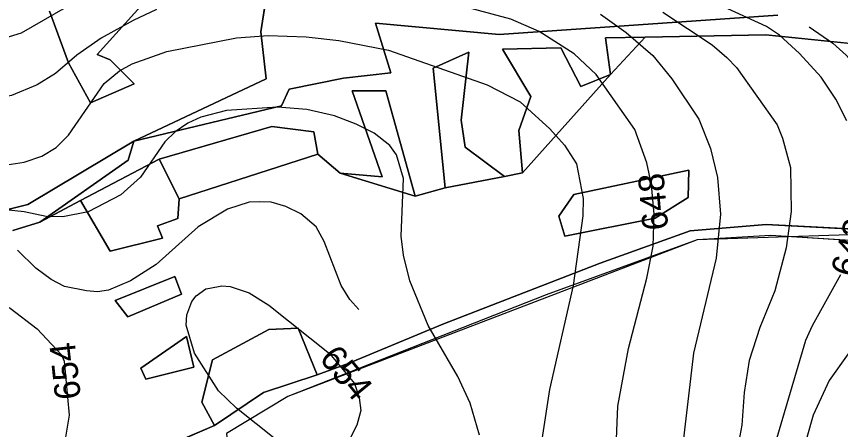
# Model space of a CAD drawing. Extents: x -709418 to -703832, y -1161719 to -1157826.
# Drawn here: x -705972.5 to -705715.8, y -1160342.6 to -1160213.8 of the extents above; entities that cross this region are included whole.
import ezdxf

# ---------------------------------------------------------------- set-up
doc = ezdxf.new("R2010")
doc.units = 0
for name, color, linetype in [('102_obvod PÚ', 7, 'Continuous'), ('120_vrstevnice hlavní', 7, 'Continuous'), ('121_vrstevnice hlavní_popis', 7, 'Continuous'), ('122_vrstevnice základní', 7, 'Continuous'), ('124_vrstevnice doplňková', 7, 'Continuous'), ('206_TTP_KN', 7, 'Continuous'), ('207_lesní pozemek_KN', 7, 'Continuous'), ('210_ostatní plocha_KN', 7, 'Continuous'), ('609_LBC_stav', 7, 'Continuous')]:
    doc.layers.add(name, color=color, linetype=linetype)

msp = doc.modelspace()

# ---------------------------------------------------------------- linework, layer by layer
at = {"layer": '102_obvod PÚ'}
for points in [[(-705735.28, -1160213.34), (-705822.05, -1160219.43), (-705860.61, -1160215.91), (-705855.83, -1160231.34), (-705870.62, -1160233.07), (-705887.55, -1160236.42), (-705889.92, -1160241.63), (-705935.88, -1160252.66), (-705894.69, -1160233.2), (-705896.39, -1160218.62), (-705894.1, -1160203.86)], [(-705894.1, -1160203.86), (-705896.39, -1160218.62), (-705894.69, -1160233.2), (-705935.88, -1160252.66), (-705889.92, -1160241.63), (-705887.55, -1160236.42), (-705870.62, -1160233.07), (-705855.83, -1160231.34), (-705860.61, -1160215.91), (-705822.05, -1160219.43), (-705735.28, -1160213.34)], [(-705690.92, -1160285.05), (-705737.52, -1160282.05), (-705760.43, -1160283.48), (-705807.45, -1160300.6), (-705887.96, -1160332.34), (-705907.02, -1160343.87), (-705903.72, -1160383.44), (-705891.24, -1160380.51), (-705892.88, -1160372.23), (-705870.76, -1160364.88), (-705872.61, -1160374.66), (-705865.48, -1160396.64), (-705851.7, -1160404.74), (-705842.93, -1160422.79), (-705826.94, -1160427.36), (-705803.04, -1160451.48), (-705774.99, -1160452.69), (-705772.92, -1160476.52), (-705777.28, -1160481.34), (-705775.29, -1160489.21), (-705766.13, -1160501.98), (-705760.34, -1160538.38)]]:
    msp.add_lwpolyline(points, dxfattribs=at)
at = {"layer": '120_vrstevnice hlavní'}
for points in [[(-705975.46, -1160260.05), (-705970.05, -1160259.2), (-705964.63, -1160257.34), (-705960.07, -1160254.64), (-705956.22, -1160250.79), (-705945.11, -1160234.69), (-705940.41, -1160230.7), (-705936.42, -1160228.56), (-705925.59, -1160224.71), (-705903.93, -1160220.44), (-705894.05, -1160219.72), (-705882.27, -1160220.15), (-705872.01, -1160221.29), (-705856.62, -1160224.29), (-705825.84, -1160235.12), (-705815.58, -1160240.39), (-705806.32, -1160248.8), (-705801.76, -1160253.93), (-705798.06, -1160259.77), (-705795.92, -1160270.6), (-705796.06, -1160276.01), (-705799.05, -1160297.67), (-705806.46, -1160330.16), (-705810.6, -1160357.23)], [(-705713.42, -1160319.05), (-705719.26, -1160327.31), (-705724.24, -1160338.14), (-705730.37, -1160359.8), (-705743.34, -1160386.87), (-705746.33, -1160397.7), (-705747.68, -1160404.55), (-705748.18, -1160413.95), (-705748.04, -1160419.36), (-705745.48, -1160430.19), (-705743.2, -1160435.61), (-705740.06, -1160441.02), (-705730.23, -1160453.42), (-705717.97, -1160466.81), (-705712.7, -1160474.08)]]:
    msp.add_lwpolyline(points, dxfattribs=at)
at = {"layer": '122_vrstevnice základní'}
for points in [[(-706139.33, -1160207.47), (-706125.22, -1160217.59), (-706114.25, -1160227.28), (-706091.31, -1160251.07), (-706082.33, -1160258.06), (-706072.36, -1160264.33), (-706060.53, -1160270.31), (-706052.12, -1160273.87), (-706033.99, -1160279.91), (-705988.29, -1160297.96), (-705974.46, -1160304.8), (-705966.06, -1160311.21), (-705960.04, -1160317.65), (-705958.49, -1160319.28), (-705957.65, -1160321.32), (-705956.08, -1160338.14), (-705957.22, -1160344.98), (-705958.93, -1160349.54), (-705966.91, -1160361.22), (-705989.85, -1160389.44), (-706003.82, -1160411.67), (-706011.94, -1160427.48), (-706030.47, -1160456.55)], [(-705928.82, -1160211.57), (-705936.13, -1160215.02), (-705946.11, -1160220.58), (-705953.66, -1160225.85), (-705960.36, -1160231.55), (-705966.06, -1160235.12), (-705974.04, -1160238.39), (-705980.02, -1160239.68), (-705984.01, -1160239.82), (-706001.97, -1160238.25), (-706021.92, -1160234.4), (-706054.12, -1160225.43), (-706068.94, -1160219.87), (-706079.48, -1160214.45), (-706090.6, -1160206.9)], [(-706008.52, -1160223.43), (-705998.55, -1160224.43), (-705988.86, -1160223.72), (-705981.16, -1160222.01), (-705970.9, -1160218.87), (-705953.8, -1160209.04)], [(-705818.43, -1160214.6), (-705834.39, -1160210.32)], [(-705713.84, -1160246.37), (-705717.26, -1160239.53), (-705721.82, -1160232.69), (-705728.52, -1160225.28), (-705734.79, -1160219.58), (-705738.78, -1160216.88), (-705752.17, -1160210.75)], [(-705790.51, -1160213.03), (-705782.53, -1160218.73), (-705774.26, -1160226), (-705768.28, -1160233.26), (-705759.87, -1160245.8), (-705756.31, -1160254.92), (-705754.03, -1160264.04), (-705753.17, -1160275.44), (-705754.45, -1160289.12), (-705761.58, -1160318.76), (-705765.28, -1160350.68)], [(-705771.12, -1160212.46), (-705755.74, -1160222.58), (-705751.2, -1160226.61), (-705748.14, -1160229.72), (-705735.45, -1160247.53), (-705733.79, -1160251.79), (-705731.37, -1160260.91), (-705731.08, -1160274.59), (-705732.65, -1160285.99), (-705736.21, -1160299.38), (-705740.92, -1160310.78), (-705744.19, -1160321.04), (-705745.76, -1160331.02), (-705746.47, -1160341.27), (-705748.33, -1160351.25)], [(-705785.66, -1160348.11), (-705785.09, -1160335.29), (-705781.81, -1160317.33), (-705776.11, -1160295.39), (-705774.12, -1160285.42), (-705773.83, -1160275.44), (-705774.69, -1160266.32), (-705776.11, -1160259.48), (-705779.82, -1160249.08), (-705791.93, -1160231.84), (-705798.77, -1160225.43), (-705809.6, -1160218.44), (-705818.43, -1160214.6)], [(-705828.27, -1160344.41), (-705831.11, -1160334.44), (-705834.96, -1160326.03), (-705844.22, -1160310.21), (-705849.92, -1160296.25), (-705851.92, -1160288.27), (-705852.63, -1160282.28), (-705851.92, -1160264.33), (-705854.06, -1160256.92), (-705856.19, -1160254.07), (-705861.04, -1160250.22), (-705866.6, -1160247.37), (-705873.44, -1160244.81), (-705881.99, -1160242.81), (-705891.11, -1160242.1), (-705907.07, -1160243.09), (-705915.05, -1160245.23), (-705919.12, -1160247.05), (-705923.02, -1160249.79), (-705926.3, -1160252.93), (-705933.85, -1160263.9), (-705939.98, -1160269.46), (-705950.1, -1160274.73), (-705958.08, -1160276.3), (-705963.21, -1160276.15), (-705970.05, -1160274.73), (-705994.5, -1160272.13)], [(-705715.41, -1160484.05), (-705720.25, -1160476.36), (-705726.81, -1160468.81), (-705737.5, -1160458.98), (-705744.76, -1160451), (-705752.25, -1160438.07), (-705754.15, -1160433.64), (-705756.73, -1160424.21), (-705757.64, -1160418.97), (-705757.59, -1160415.09), (-705757.45, -1160408.25), (-705754.88, -1160394.57), (-705751.18, -1160383.17), (-705740.06, -1160358.09), (-705736.64, -1160348.97), (-705726.52, -1160314.77), (-705724.53, -1160310.21), (-705715.7, -1160294.25)], [(-705909.49, -1160330.59), (-705917.04, -1160318.76), (-705919.6, -1160310.04), (-705919.44, -1160306.86), (-705917.89, -1160302.73), (-705916.48, -1160300.97), (-705913.45, -1160298.77), (-705912.2, -1160298.53), (-705908.49, -1160297.81), (-705905.93, -1160297.96), (-705899.94, -1160299.95), (-705893.81, -1160303.8), (-705875, -1160318.9), (-705867.17, -1160328.31), (-705865.74, -1160332.73), (-705865.17, -1160336.72), (-705866.45, -1160341.27), (-705868.82, -1160345.93)], [(-705891.68, -1160345.69), (-705903.93, -1160336), (-705909.49, -1160330.59)]]:
    msp.add_lwpolyline(points, dxfattribs=at)
at = {"layer": '124_vrstevnice doplňková'}
for points in [[(-705725.51, -1160216.98), (-705718.12, -1160222.15), (-705713.98, -1160225.85), (-705709.99, -1160230.41), (-705703.3, -1160239.82), (-705698.17, -1160252.64), (-705696.17, -1160262.62), (-705696.46, -1160274.02), (-705697.74, -1160280.86), (-705702.3, -1160290.4)], [(-705865.86, -1160305.15), (-705868.59, -1160302.09), (-705871.3, -1160297.67), (-705876.57, -1160283.99), (-705879.14, -1160279.43), (-705883.84, -1160275.3), (-705888.54, -1160273.02), (-705893.1, -1160271.74), (-705896.77, -1160271.62), (-705899.94, -1160271.74), (-705906.78, -1160273.87), (-705915.9, -1160279.43), (-705929.01, -1160291.12), (-705936.99, -1160296.25), (-705943.83, -1160299.1), (-705947.24, -1160299.72), (-705950.67, -1160299.38), (-705957.51, -1160297.96), (-705961.64, -1160295.82), (-705966.48, -1160292.26), (-705972.18, -1160286.7)]]:
    msp.add_lwpolyline(points, dxfattribs=at)
at = {"layer": '206_TTP_KN'}
for points in [[(-705894.1, -1160203.86), (-705896.39, -1160218.62), (-705894.69, -1160233.2), (-705935.88, -1160252.66), (-705968.89, -1160272.43), (-706006.54, -1160281.78), (-706042.5, -1160286.16), (-706098.09, -1160287.95), (-706104.62, -1160239.75), (-706122.98, -1160227.78), (-706120.14, -1160191.95)], [(-705962.19, -1160212.13), (-705956.28, -1160228.2), (-705949.41, -1160240.72), (-705935.86, -1160234.78), (-705943.25, -1160227.28), (-705947.39, -1160225.61), (-705932.85, -1160209.48)], [(-705973.63, -1160280.5), (-705965.16, -1160277.89), (-705952.5, -1160271.23), (-705943.28, -1160287), (-705926.96, -1160282.94), (-705928.59, -1160279.04), (-705922.18, -1160276.8), (-705921.76, -1160270.62), (-705878.58, -1160256.78), (-705871.67, -1160262.68), (-705848.28, -1160269.81), (-705838.93, -1160267.21), (-705820.39, -1160263.68), (-705814.83, -1160262.54), (-705787.37, -1160231.9), (-705776.61, -1160220.22), (-705739.07, -1160219.48), (-705709.54, -1160222.57)], [(-705803.55, -1160276.02), (-705801.64, -1160282.32), (-705773.54, -1160276.72), (-705763.21, -1160270.28), (-705763, -1160261.72), (-705798.81, -1160269.29), (-705803.55, -1160276.02)], [(-705690.96, -1160281.19), (-705738.93, -1160278.67), (-705762.57, -1160280.65), (-705790.67, -1160290.77), (-705839.64, -1160309.74), (-705869.16, -1160321.98), (-705878.78, -1160325.59), (-705884.75, -1160311.03), (-705893.91, -1160311.39), (-705911.39, -1160320.83), (-705914.75, -1160334.07), (-705910.77, -1160341.38), (-705941.4, -1160354.48), (-705982.09, -1160362.19), (-705988.37, -1160348.37), (-705988.94, -1160332.52), (-705995.59, -1160334.33), (-705996.39, -1160363.25), (-706013.23, -1160364.81), (-706055.06, -1160369.06), (-706082.24, -1160372.31), (-706147.28, -1160379.75), (-706201.14, -1160395.86)], [(-705941.7, -1160302.34), (-705937.81, -1160307.51), (-705921.11, -1160300.36), (-705923.16, -1160294.84), (-705941.7, -1160302.34)], [(-705933.7, -1160323.44), (-705932.22, -1160326.9), (-705917.21, -1160323.22), (-705919.48, -1160313.6), (-705933.7, -1160323.44)]]:
    msp.add_lwpolyline(points, dxfattribs=at)
at = {"layer": '207_lesní pozemek_KN'}
for p, q in [((-705896.39, -1160218.62), (-705894.1, -1160203.86)), ((-705735.28, -1160213.34), (-705822.05, -1160219.43)), ((-705822.05, -1160219.43), (-705860.61, -1160215.91)), ((-705860.61, -1160215.91), (-705855.83, -1160231.34)), ((-705894.69, -1160233.2), (-705896.39, -1160218.62)), ((-705789, -1160220.47), (-705776.61, -1160220.22)), ((-705787.37, -1160231.9), (-705789, -1160220.47)), ((-705776.61, -1160220.22), (-705787.37, -1160231.9)), ((-705821.09, -1160223.97), (-705802.94, -1160223.51)), ((-705812.28, -1160238.73), (-705821.09, -1160223.97)), ((-705802.94, -1160223.51), (-705796.61, -1160235.61)), ((-705842.71, -1160229.92), (-705831.57, -1160224.89)), ((-705831.57, -1160224.89), (-705833.94, -1160246.09)), ((-705855.83, -1160231.34), (-705870.62, -1160233.07)), ((-705838.93, -1160267.21), (-705842.71, -1160229.92)), ((-705787.37, -1160231.9), (-705814.83, -1160262.54)), ((-705796.61, -1160235.61), (-705787.37, -1160231.9)), ((-705935.88, -1160252.66), (-705894.69, -1160233.2)), ((-705870.62, -1160233.07), (-705887.55, -1160236.42)), ((-705887.55, -1160236.42), (-705889.92, -1160241.63)), ((-705858.51, -1160263.85), (-705867.86, -1160236.96)), ((-705867.86, -1160236.96), (-705857.46, -1160236.96)), ((-705857.46, -1160236.96), (-705848.28, -1160269.81)), ((-705816, -1160249.31), (-705812.28, -1160238.73)), ((-705889.92, -1160241.63), (-705935.88, -1160252.66)), ((-705833.94, -1160246.09), (-705832.74, -1160254.55)), ((-705927.98, -1160258.34), (-705892.92, -1160248.08)), ((-705892.92, -1160248.08), (-705879.89, -1160249.77)), ((-705879.89, -1160249.77), (-705878.58, -1160256.78)), ((-705814.83, -1160262.54), (-705816, -1160249.31)), ((-705832.74, -1160254.55), (-705820.39, -1160263.68)), ((-705878.58, -1160256.78), (-705921.76, -1160270.62)), ((-705952.5, -1160271.23), (-705927.98, -1160258.34)), ((-705927.98, -1160258.34), (-705921.76, -1160270.62)), ((-705921.76, -1160270.62), (-705927.98, -1160258.34)), ((-705871.67, -1160262.68), (-705858.51, -1160263.85)), ((-705848.28, -1160269.81), (-705871.67, -1160262.68)), ((-705820.39, -1160263.68), (-705838.93, -1160267.21)), ((-705921.76, -1160270.62), (-705922.18, -1160276.8)), ((-705943.28, -1160287), (-705952.5, -1160271.23)), ((-705922.18, -1160276.8), (-705928.59, -1160279.04)), ((-705928.59, -1160279.04), (-705926.96, -1160282.94)), ((-705926.96, -1160282.94), (-705943.28, -1160287)), ((-705911.39, -1160320.83), (-705893.91, -1160311.39)), ((-705893.91, -1160311.39), (-705884.75, -1160311.03)), ((-705884.75, -1160311.03), (-705878.78, -1160325.59)), ((-705914.75, -1160334.07), (-705911.39, -1160320.83)), ((-705878.78, -1160325.59), (-705895.56, -1160331.04)), ((-705895.56, -1160331.04), (-705910.77, -1160341.38)), ((-705910.77, -1160341.38), (-705914.75, -1160334.07))]:
    msp.add_line(p, q, dxfattribs=at)
at = {"layer": '210_ostatní plocha_KN'}
for p, q in [((-705932.85, -1160209.48), (-705947.39, -1160225.61)), ((-705956.28, -1160228.2), (-705962.19, -1160212.13)), ((-705822.05, -1160219.43), (-705735.28, -1160213.34)), ((-705855.83, -1160231.34), (-705860.61, -1160215.91)), ((-705860.61, -1160215.91), (-705822.05, -1160219.43)), ((-705776.61, -1160220.22), (-705789, -1160220.47)), ((-705789, -1160220.47), (-705787.37, -1160231.9)), ((-705739.07, -1160219.48), (-705776.61, -1160220.22)), ((-705709.54, -1160222.57), (-705739.07, -1160219.48)), ((-705802.94, -1160223.51), (-705821.09, -1160223.97)), ((-705821.09, -1160223.97), (-705812.28, -1160238.73)), ((-705796.61, -1160235.61), (-705802.94, -1160223.51)), ((-705947.39, -1160225.61), (-705943.25, -1160227.28)), ((-705831.57, -1160224.89), (-705842.71, -1160229.92)), ((-705833.94, -1160246.09), (-705831.57, -1160224.89)), ((-705949.41, -1160240.72), (-705956.28, -1160228.2)), ((-705943.25, -1160227.28), (-705935.86, -1160234.78)), ((-705870.62, -1160233.07), (-705855.83, -1160231.34)), ((-705842.71, -1160229.92), (-705838.93, -1160267.21)), ((-705787.37, -1160231.9), (-705796.61, -1160235.61)), ((-705887.55, -1160236.42), (-705870.62, -1160233.07)), ((-705935.86, -1160234.78), (-705949.41, -1160240.72)), ((-705889.92, -1160241.63), (-705887.55, -1160236.42)), ((-705857.46, -1160236.96), (-705867.86, -1160236.96)), ((-705867.86, -1160236.96), (-705858.51, -1160263.85)), ((-705848.28, -1160269.81), (-705857.46, -1160236.96)), ((-705812.28, -1160238.73), (-705816, -1160249.31)), ((-705935.88, -1160252.66), (-705889.92, -1160241.63)), ((-705832.74, -1160254.55), (-705833.94, -1160246.09)), ((-705892.92, -1160248.08), (-705927.98, -1160258.34)), ((-705879.89, -1160249.77), (-705892.92, -1160248.08)), ((-705878.58, -1160256.78), (-705879.89, -1160249.77)), ((-705816, -1160249.31), (-705814.83, -1160262.54)), ((-705968.89, -1160272.43), (-705935.88, -1160252.66)), ((-705935.88, -1160252.66), (-705937.64, -1160258.64)), ((-705937.64, -1160258.64), (-705935.88, -1160252.66)), ((-705820.39, -1160263.68), (-705832.74, -1160254.55)), ((-705871.67, -1160262.68), (-705878.58, -1160256.78)), ((-705937.64, -1160258.64), (-705965.16, -1160277.89)), ((-705965.16, -1160277.89), (-705937.64, -1160258.64)), ((-705927.98, -1160258.34), (-705952.5, -1160271.23)), ((-705858.51, -1160263.85), (-705871.67, -1160262.68)), ((-705814.83, -1160262.54), (-705820.39, -1160263.68)), ((-705798.81, -1160269.29), (-705763, -1160261.72)), ((-705763, -1160261.72), (-705763.21, -1160270.28)), ((-705838.93, -1160267.21), (-705848.28, -1160269.81)), ((-705803.55, -1160276.02), (-705798.81, -1160269.29)), ((-705763.21, -1160270.28), (-705773.54, -1160276.72)), ((-706006.54, -1160281.78), (-705968.89, -1160272.43)), ((-705952.5, -1160271.23), (-705965.16, -1160277.89)), ((-705965.16, -1160277.89), (-705973.63, -1160280.5)), ((-705801.64, -1160282.32), (-705803.55, -1160276.02)), ((-705773.54, -1160276.72), (-705801.64, -1160282.32)), ((-705790.67, -1160290.77), (-705762.57, -1160280.65)), ((-705762.57, -1160280.65), (-705738.93, -1160278.67)), ((-705738.93, -1160278.67), (-705690.96, -1160281.19)), ((-705760.43, -1160283.48), (-705807.45, -1160300.6)), ((-705737.52, -1160282.05), (-705760.43, -1160283.48)), ((-705690.92, -1160285.05), (-705737.52, -1160282.05)), ((-705839.64, -1160309.74), (-705790.67, -1160290.77)), ((-705941.7, -1160302.34), (-705923.16, -1160294.84)), ((-705923.16, -1160294.84), (-705921.11, -1160300.36)), ((-705921.11, -1160300.36), (-705937.81, -1160307.51)), ((-705807.45, -1160300.6), (-705887.96, -1160332.34)), ((-705937.81, -1160307.51), (-705941.7, -1160302.34)), ((-705869.16, -1160321.98), (-705839.64, -1160309.74)), ((-705933.7, -1160323.44), (-705919.48, -1160313.6)), ((-705919.48, -1160313.6), (-705917.21, -1160323.22)), ((-705878.78, -1160325.59), (-705869.16, -1160321.98)), ((-705932.22, -1160326.9), (-705933.7, -1160323.44)), ((-705917.21, -1160323.22), (-705932.22, -1160326.9)), ((-705895.56, -1160331.04), (-705878.78, -1160325.59)), ((-705910.77, -1160341.38), (-705895.56, -1160331.04)), ((-705887.96, -1160332.34), (-705907.02, -1160343.87)), ((-705941.4, -1160354.48), (-705910.77, -1160341.38))]:
    msp.add_line(p, q, dxfattribs=at)
at = {"layer": '609_LBC_stav'}
msp.add_lwpolyline([(-705690.96, -1160281.19), (-705760.43, -1160283.48), (-705887.96, -1160332.34), (-705907.02, -1160343.87), (-705903.72, -1160383.44), (-705891.24, -1160380.51), (-705892.88, -1160372.23), (-705870.76, -1160364.88), (-705865.48, -1160396.64), (-705851.7, -1160404.74), (-705842.93, -1160422.79), (-705826.94, -1160427.36), (-705803.04, -1160451.48), (-705774.99, -1160452.69), (-705772.92, -1160476.52), (-705777.28, -1160481.34), (-705766.13, -1160501.98), (-705760.34, -1160538.38), (-705784.66, -1160537.3), (-705792.04, -1160572.56), (-705797.87, -1160642.09), (-705816.86, -1160685.82), (-705732.66, -1160722.96)], dxfattribs=at)

# ---------------------------------------------------------------- texts
at = {"layer": '121_vrstevnice hlavní_popis'}
for s, rotation, p in [('648', 94.9818, (-705769.38, -1160280.14)), ('642', 74.6189, (-705711.24, -1160295.49)), ('654', 96.219, (-705952.38, -1160332.86)), ('654', 309.2945, (-705878.41, -1160320.52))]:
    msp.add_text(s, height=8, rotation=rotation, dxfattribs=at).set_placement(p)

doc.saveas('drawing.dxf')
